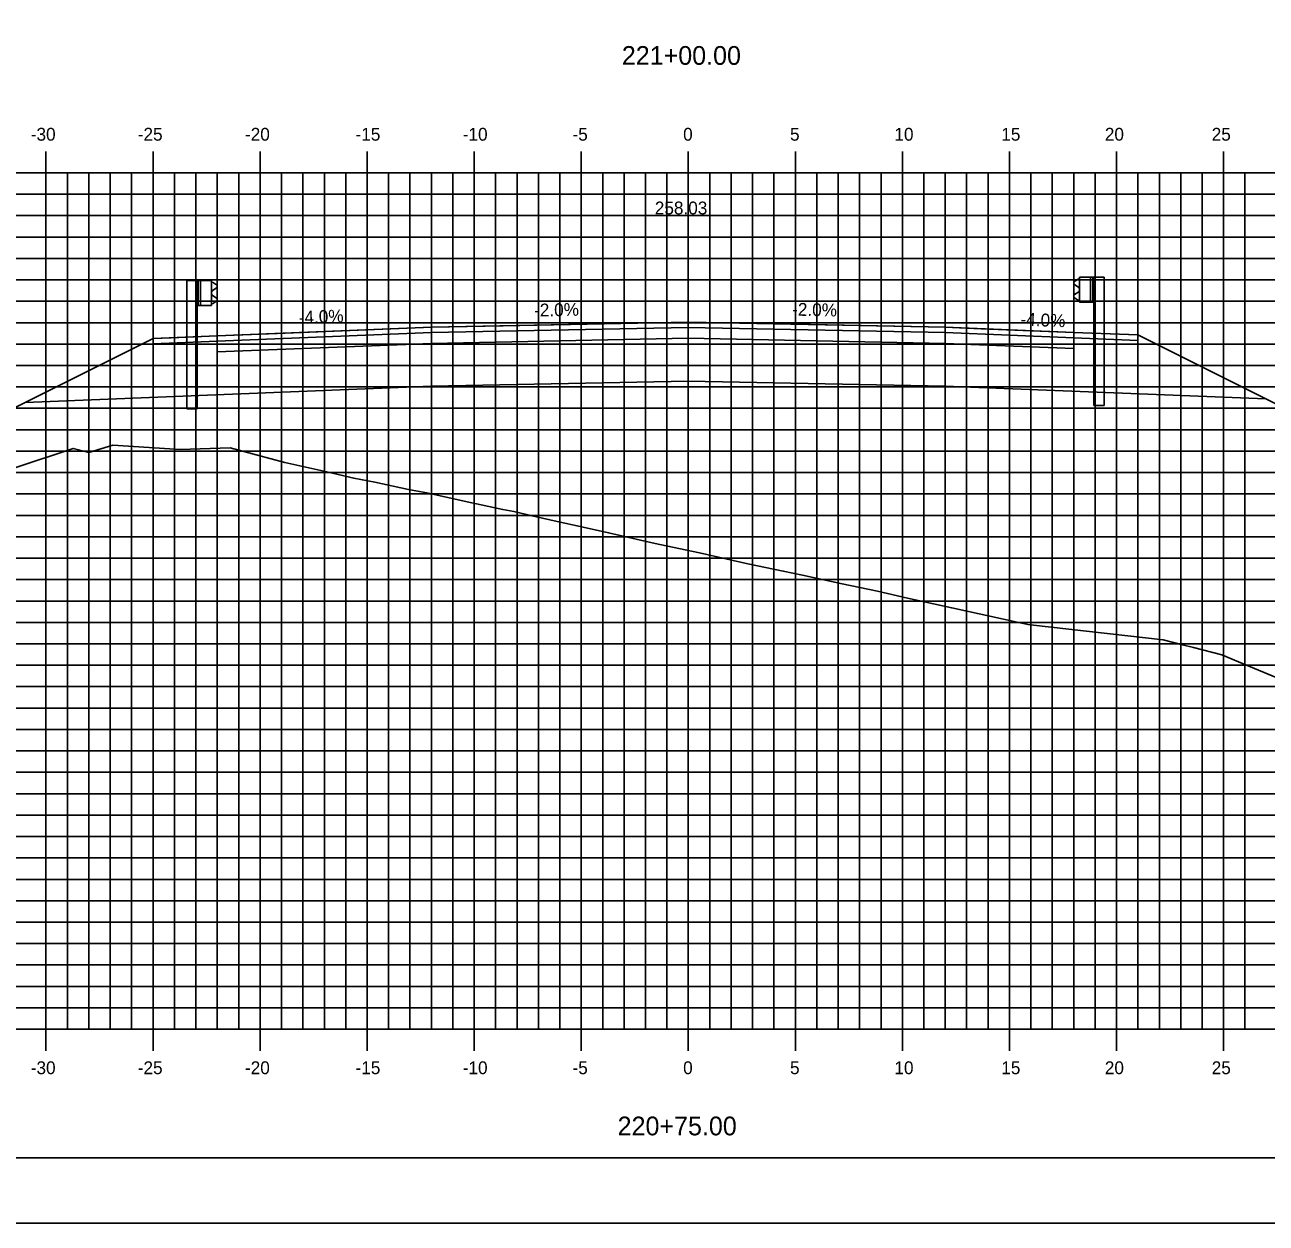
# Model space of a CAD drawing. Extents: x -22 to 1480, y -1511 to 8.
# Drawn here: x 917 to 975, y -184.5 to -128.6 of the extents above; entities that cross this region are included whole.
import ezdxf

# ---------------------------------------------------------------- set-up
doc = ezdxf.new("R2010")
doc.units = 0
for name, color, linetype in [('ANNOTATION', 7, 'Continuous'), ('BORDER', 7, 'Continuous'), ('D_Guardrail_Beam_Lt', 7, 'Continuous'), ('D_Guardrail_Beam_Rt', 7, 'Continuous'), ('D_Roadway_Centerline', 7, 'Continuous'), ('D_Roadway_Centerline_Text', 7, 'Continuous'), ('D_Roadway_Edge_Shoulder', 7, 'Continuous'), ('D_Roadway_Edge_TW', 7, 'Continuous'), ('D_Roadway_Pavement', 7, 'Continuous'), ('D_Roadway_SubGrade', 7, 'Continuous'), ('H_V ANNOTATION', 7, 'Continuous'), ('MAJOR', 7, 'Continuous'), ('MINOR', 7, 'Continuous'), ('PLOT BOUNDARY', 7, 'Continuous'), ('S_Roadway_Centerline', 7, 'Continuous')]:
    doc.layers.add(name, color=color, linetype=linetype)

msp = doc.modelspace()

# ---------------------------------------------------------------- linework, layer by layer
at = {"layer": 'BORDER'}
msp.add_line((872.966, -181.466), (1032.966, -181.466), dxfattribs=at)
at = {"layer": 'D_Guardrail_Beam_Lt'}
for p, q in [((966.146, -140.442), (966.003, -140.542)), ((966.003, -140.685), (966.198, -140.821)), ((966.236, -140.421), (966.162, -140.435)), ((966.232, -140.886), (966.232, -140.956)), ((966.236, -140.337), (966.924, -140.337)), ((966.236, -141.504), (966.236, -140.337)), ((966.757, -140.337), (966.757, -141.504)), ((966.861, -140.337), (966.861, -141.504)), ((966.924, -140.337), (967.394, -140.337)), ((966.924, -140.337), (966.924, -141.504)), ((967.394, -140.337), (967.394, -146.337)), ((966.198, -141.02), (966.003, -141.156)), ((966.003, -141.299), (966.146, -141.399)), ((966.162, -141.406), (966.236, -141.421)), ((966.924, -141.504), (966.236, -141.504)), ((966.903, -146.337), (966.903, -141.504)), ((966.903, -146.337), (967.394, -146.337))]:
    msp.add_line(p, q, dxfattribs=at)
for centre, major_axis, start_param, end_param in [((966.053, -140.613), (-0.0877, 0), 5.323254, 7.243116), ((966.17, -140.476), (-0.0417, 0), 4.907132, 5.323254), ((966.153, -140.886), (0.0789, 0), 0, 0.959931), ((966.053, -141.228), (-0.0877, 0), 5.323254, 7.243116), ((966.17, -141.365), (-0.0417, 0), 0.959931, 1.376053), ((966.153, -140.956), (0.0789, 0), 5.323254, 6.283185)]:
    msp.add_ellipse(centre, major_axis=major_axis, ratio=0.995501, start_param=start_param, end_param=end_param, dxfattribs=at)
at = {"layer": 'D_Guardrail_Beam_Rt'}
for p, q in [((924.536, -140.497), (924.536, -146.497)), ((925.007, -140.497), (924.536, -140.497)), ((925.694, -140.497), (925.007, -140.497)), ((925.007, -140.497), (925.007, -141.664)), ((925.069, -140.497), (925.069, -141.664)), ((925.174, -140.497), (925.174, -141.664)), ((925.694, -141.664), (925.694, -140.497)), ((925.694, -140.581), (925.769, -140.595)), ((925.928, -140.845), (925.733, -140.981)), ((925.784, -140.602), (925.928, -140.702)), ((925.699, -141.046), (925.699, -141.116)), ((925.733, -141.18), (925.928, -141.316)), ((925.928, -141.459), (925.784, -141.559)), ((925.007, -141.664), (925.694, -141.664)), ((925.028, -146.497), (925.028, -141.664)), ((925.769, -141.566), (925.694, -141.581)), ((925.028, -146.497), (924.536, -146.497))]:
    msp.add_line(p, q, dxfattribs=at)
for centre, major_axis, start_param, end_param in [((925.761, -140.636), (0.0417, 0), 0.959931, 1.376053), ((925.878, -140.773), (0.0877, 0), 5.323254, 7.243116), ((925.778, -141.046), (-0.0789, 0), 5.323254, 6.283185), ((925.778, -141.116), (-0.0789, 0), 6.283185, 7.243116), ((925.878, -141.388), (0.0877, 0), 5.323254, 7.243116), ((925.761, -141.525), (0.0417, 0), 4.907132, 5.323254)]:
    msp.add_ellipse(centre, major_axis=major_axis, ratio=0.995501, start_param=start_param, end_param=end_param, dxfattribs=at)
at = {"layer": 'D_Roadway_Centerline'}
msp.add_lwpolyline([(901.312, -154.027), (916.987, -146.19), (922.965, -143.201), (923.805, -143.167), (925.965, -143.081), (928.765, -142.969), (935.965, -142.681), (939.325, -142.613), (947.965, -142.441), (951.325, -142.508), (959.965, -142.681), (961.645, -142.748), (965.965, -142.921), (966.805, -142.954), (968.965, -143.041), (970.639, -143.878), (974.944, -146.03), (980.603, -148.86), (981.929, -149.523), (981.929, -149.023), (983.429, -149.023)], dxfattribs=at)
at = {"layer": 'D_Roadway_Edge_Shoulder'}
for points in [[(935.965, -142.681), (925.965, -143.081), (925.965, -143.081), (922.965, -143.201), (922.965, -143.451), (925.965, -143.331), (925.965, -143.331), (935.965, -142.931)], [(959.965, -142.681), (965.965, -142.921), (965.965, -142.921), (968.965, -143.041), (968.965, -143.291), (965.965, -143.171), (965.965, -143.171), (959.965, -142.931)]]:
    msp.add_lwpolyline(points, close=True, dxfattribs=at)
at = {"layer": 'D_Roadway_Edge_TW'}
msp.add_lwpolyline([(959.965, -142.931), (959.965, -142.681), (947.965, -142.441), (935.965, -142.681), (935.965, -142.931), (947.965, -142.691)], close=True, dxfattribs=at)
at = {"layer": 'D_Roadway_Pavement'}
for points in [[(935.965, -142.931), (925.965, -143.331), (925.965, -143.331), (925.965, -143.831), (935.965, -143.431), (935.965, -142.931)], [(959.965, -142.931), (965.965, -143.171), (965.965, -143.171), (965.965, -143.671), (959.965, -143.431), (959.965, -142.931)]]:
    msp.add_lwpolyline(points, dxfattribs=at)
msp.add_lwpolyline([(959.965, -143.431), (959.965, -142.931), (947.965, -142.691), (935.965, -142.931), (935.965, -143.431), (947.965, -143.191)], close=True, dxfattribs=at)
at = {"layer": 'D_Roadway_SubGrade'}
for points in [[(935.965, -143.431), (925.965, -143.831), (925.965, -143.331), (922.965, -143.451), (922.965, -143.201), (916.987, -146.19), (935.965, -145.431)], [(959.965, -145.431), (959.965, -143.431), (947.965, -143.191), (935.965, -143.431), (935.965, -145.431), (947.965, -145.191)], [(959.965, -143.431), (965.965, -143.671), (965.965, -143.171), (968.965, -143.291), (968.965, -143.041), (974.944, -146.03), (959.965, -145.431)]]:
    msp.add_lwpolyline(points, close=True, dxfattribs=at)
at = {"layer": 'MAJOR'}
for p, q in [((917.965, -134.464), (917.965, -135.466)), ((922.965, -134.464), (922.965, -135.466)), ((927.965, -134.464), (927.965, -135.466)), ((932.965, -134.464), (932.965, -135.466)), ((937.965, -134.464), (937.965, -135.466)), ((942.965, -134.464), (942.965, -135.466)), ((947.965, -134.464), (947.965, -135.466)), ((952.965, -134.464), (952.965, -135.466)), ((957.965, -134.464), (957.965, -135.466)), ((962.965, -134.464), (962.965, -135.466)), ((967.965, -134.464), (967.965, -135.466)), ((972.965, -134.464), (972.965, -135.466)), ((877.965, -135.466), (1017.965, -135.466)), ((877.965, -135.466), (1017.965, -135.466)), ((917.965, -175.466), (917.965, -135.466)), ((922.965, -175.466), (922.965, -135.466)), ((927.965, -175.466), (927.965, -135.466)), ((932.965, -175.466), (932.965, -135.466)), ((937.965, -175.466), (937.965, -135.466)), ((942.965, -175.466), (942.965, -135.466)), ((947.965, -175.466), (947.965, -135.466)), ((952.965, -175.466), (952.965, -135.466)), ((957.965, -175.466), (957.965, -135.466)), ((962.965, -175.466), (962.965, -135.466)), ((967.965, -175.466), (967.965, -135.466)), ((972.965, -175.466), (972.965, -135.466)), ((877.965, -140.466), (1017.965, -140.466)), ((877.965, -145.466), (1017.965, -145.466)), ((877.965, -150.466), (1017.965, -150.466)), ((877.965, -155.466), (1017.965, -155.466)), ((877.965, -160.466), (1017.965, -160.466)), ((877.965, -165.466), (1017.965, -165.466)), ((877.965, -170.466), (1017.965, -170.466)), ((877.965, -175.466), (1017.965, -175.466)), ((877.965, -175.466), (1017.965, -175.466)), ((917.965, -176.468), (917.965, -175.466)), ((922.965, -176.468), (922.965, -175.466)), ((927.965, -176.468), (927.965, -175.466)), ((932.965, -176.468), (932.965, -175.466)), ((937.965, -176.468), (937.965, -175.466)), ((942.965, -176.468), (942.965, -175.466)), ((947.965, -176.468), (947.965, -175.466)), ((952.965, -176.468), (952.965, -175.466)), ((957.965, -176.468), (957.965, -175.466)), ((962.965, -176.468), (962.965, -175.466)), ((967.965, -176.468), (967.965, -175.466)), ((972.965, -176.468), (972.965, -175.466))]:
    msp.add_line(p, q, dxfattribs=at)
at = {"layer": 'MINOR'}
for p, q in [((918.965, -175.466), (918.965, -135.466)), ((919.965, -175.466), (919.965, -135.466)), ((920.965, -175.466), (920.965, -135.466)), ((921.965, -175.466), (921.965, -135.466)), ((923.965, -175.466), (923.965, -135.466)), ((924.965, -175.466), (924.965, -135.466)), ((925.965, -175.466), (925.965, -135.466)), ((926.965, -175.466), (926.965, -135.466)), ((928.965, -175.466), (928.965, -135.466)), ((929.965, -175.466), (929.965, -135.466)), ((930.965, -175.466), (930.965, -135.466)), ((931.965, -175.466), (931.965, -135.466)), ((933.965, -175.466), (933.965, -135.466)), ((934.965, -175.466), (934.965, -135.466)), ((935.965, -175.466), (935.965, -135.466)), ((936.965, -175.466), (936.965, -135.466)), ((938.965, -175.466), (938.965, -135.466)), ((939.965, -175.466), (939.965, -135.466)), ((940.965, -175.466), (940.965, -135.466)), ((941.965, -175.466), (941.965, -135.466)), ((943.965, -175.466), (943.965, -135.466)), ((944.965, -175.466), (944.965, -135.466)), ((945.965, -175.466), (945.965, -135.466)), ((946.965, -175.466), (946.965, -135.466)), ((948.965, -175.466), (948.965, -135.466)), ((949.965, -175.466), (949.965, -135.466)), ((950.965, -175.466), (950.965, -135.466)), ((951.965, -175.466), (951.965, -135.466)), ((953.965, -175.466), (953.965, -135.466)), ((954.965, -175.466), (954.965, -135.466)), ((955.965, -175.466), (955.965, -135.466)), ((956.965, -175.466), (956.965, -135.466)), ((958.965, -175.466), (958.965, -135.466)), ((959.965, -175.466), (959.965, -135.466)), ((960.965, -175.466), (960.965, -135.466)), ((961.965, -175.466), (961.965, -135.466)), ((963.965, -175.466), (963.965, -135.466)), ((964.965, -175.466), (964.965, -135.466)), ((965.965, -175.466), (965.965, -135.466)), ((966.965, -175.466), (966.965, -135.466)), ((968.965, -175.466), (968.965, -135.466)), ((969.965, -175.466), (969.965, -135.466)), ((970.965, -175.466), (970.965, -135.466)), ((971.965, -175.466), (971.965, -135.466)), ((973.965, -175.466), (973.965, -135.466)), ((877.965, -136.466), (1017.965, -136.466)), ((877.965, -137.466), (1017.965, -137.466)), ((877.965, -138.466), (1017.965, -138.466)), ((877.965, -139.466), (1017.965, -139.466)), ((877.965, -141.466), (1017.965, -141.466)), ((877.965, -142.466), (1017.965, -142.466)), ((877.965, -143.466), (1017.965, -143.466)), ((877.965, -144.466), (1017.965, -144.466)), ((877.965, -146.466), (1017.965, -146.466)), ((877.965, -147.466), (1017.965, -147.466)), ((877.965, -148.466), (1017.965, -148.466)), ((877.965, -149.466), (1017.965, -149.466)), ((877.965, -151.466), (1017.965, -151.466)), ((877.965, -152.466), (1017.965, -152.466)), ((877.965, -153.466), (1017.965, -153.466)), ((877.965, -154.466), (1017.965, -154.466)), ((877.965, -156.466), (1017.965, -156.466)), ((877.965, -157.466), (1017.965, -157.466)), ((877.965, -158.466), (1017.965, -158.466)), ((877.965, -159.466), (1017.965, -159.466)), ((877.965, -161.466), (1017.965, -161.466)), ((877.965, -162.466), (1017.965, -162.466)), ((877.965, -163.466), (1017.965, -163.466)), ((877.965, -164.466), (1017.965, -164.466)), ((877.965, -166.466), (1017.965, -166.466)), ((877.965, -167.466), (1017.965, -167.466)), ((877.965, -168.466), (1017.965, -168.466)), ((877.965, -169.466), (1017.965, -169.466)), ((877.965, -171.466), (1017.965, -171.466)), ((877.965, -172.466), (1017.965, -172.466)), ((877.965, -173.466), (1017.965, -173.466)), ((877.965, -174.466), (1017.965, -174.466))]:
    msp.add_line(p, q, dxfattribs=at)
at = {"layer": 'PLOT BOUNDARY'}
msp.add_lwpolyline([(864.872, -184.525), (1034.872, -184.525), (1034.872, -74.525), (864.872, -74.525)], close=True, dxfattribs=at)
at = {"layer": 'S_Roadway_Centerline'}
msp.add_lwpolyline([(902.458, -153.894), (919.235, -148.34), (919.97, -148.522), (921.091, -148.185), (924.233, -148.384), (926.564, -148.316), (928.647, -148.868), (929.126, -148.997), (931.082, -149.44), (932.341, -149.729), (933.327, -149.923), (934.901, -150.252), (935.747, -150.42), (937.635, -150.828), (939.3, -151.187), (939.812, -151.293), (940.67, -151.49), (941.987, -151.786), (942.772, -151.959), (944.241, -152.276), (946.276, -152.747), (946.641, -152.827), (948.49, -153.216), (949.716, -153.489), (950.746, -153.737), (952.398, -154.066), (953.304, -154.261), (955.152, -154.663), (956.803, -155.014), (958.196, -155.327), (960.272, -155.786), (963.332, -156.451), (963.76, -156.544), (963.83, -156.559), (963.94, -156.574), (970.147, -157.281), (971.043, -157.51), (971.563, -157.642), (972.889, -157.98), (973.656, -158.303), (975.605, -159.123)], dxfattribs=at)

# ---------------------------------------------------------------- texts
at = {"layer": 'ANNOTATION'}
for s, rotation, p in [('-4.0%', 2.29061, (929.781, -142.527)), ('-2.0%', 1.14576, (940.768, -142.184)), ('-2.0%', 358.85424, (952.808, -142.137)), ('-4.0%', 357.70939, (963.472, -142.597))]:
    msp.add_text(s, height=0.6, rotation=rotation, dxfattribs=at).set_placement(p)
at = {"layer": 'D_Roadway_Centerline'}
for s, p in [('C', (947.96, -142.441)), ('L', (947.965, -142.448))]:
    msp.add_text(s, height=0.0146, dxfattribs=at).set_placement(p)
at = {"layer": 'D_Roadway_Centerline_Text'}
msp.add_text('258.03', height=0.6, dxfattribs=at).set_placement((946.4, -137.409))
at = {"layer": 'H_V ANNOTATION'}
for s, height, p in [('221+00.00', 0.875, (944.86, -130.423)), ('-30', 0.6, (917.254, -133.966)), ('-25', 0.6, (922.251, -133.966)), ('-20', 0.6, (927.259, -133.966)), ('-15', 0.6, (932.422, -133.966)), ('-10', 0.6, (937.43, -133.966)), ('-5', 0.6, (942.556, -133.966)), ('0', 0.6, (947.724, -133.966)), ('5', 0.6, (952.716, -133.966)), ('10', 0.6, (957.591, -133.966)), ('15', 0.6, (962.583, -133.966)), ('20', 0.6, (967.419, -133.966)), ('25', 0.6, (972.411, -133.966)), ('-30', 0.6, (917.254, -177.566)), ('-25', 0.6, (922.251, -177.566)), ('-20', 0.6, (927.259, -177.566)), ('-15', 0.6, (932.422, -177.566)), ('-10', 0.6, (937.43, -177.566)), ('-5', 0.6, (942.556, -177.566)), ('0', 0.6, (947.724, -177.566)), ('5', 0.6, (952.716, -177.566)), ('10', 0.6, (957.591, -177.566)), ('15', 0.6, (962.583, -177.566)), ('20', 0.6, (967.419, -177.566)), ('25', 0.6, (972.411, -177.566)), ('220+75.00', 0.875, (944.664, -180.423))]:
    msp.add_text(s, height=height, dxfattribs=at).set_placement(p)

doc.saveas('drawing.dxf')
